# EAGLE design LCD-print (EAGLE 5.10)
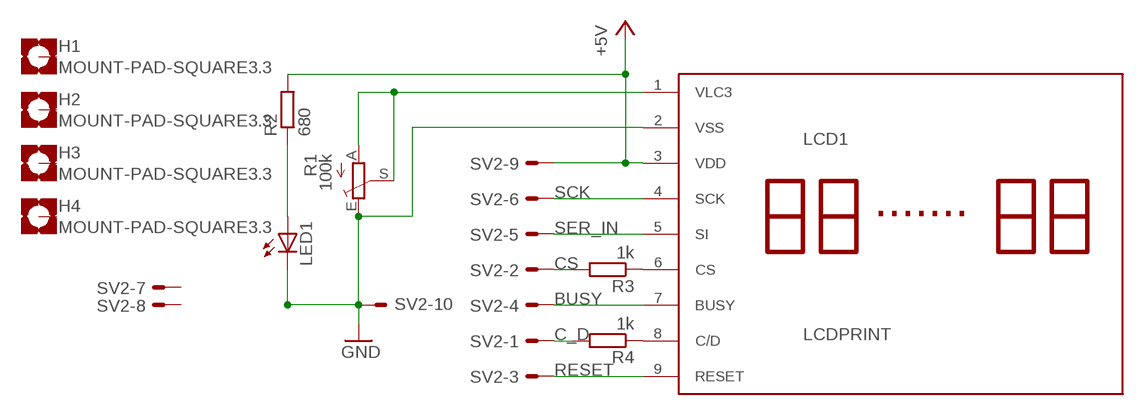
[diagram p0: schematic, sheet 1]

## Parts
H1  MOUNT-PAD-SQUARE3.3  [3,3-PAD-SQUARE]
H2  MOUNT-PAD-SQUARE3.3  [3,3-PAD-SQUARE]
H3  MOUNT-PAD-SQUARE3.3  [3,3-PAD-SQUARE]
H4  MOUNT-PAD-SQUARE3.3  [3,3-PAD-SQUARE]
LCD1  LCDPRINT  [LCD-PRINT]
LED1  LED5MM  [LED5MM]
R1  100k  TRIM_EU-CA6H  [CA6H]
R2  680  R-EU_0207/10  [0207/10]
R3  1k  R-EU_0207/10  [0207/10]
R4  1k  R-EU_0207/10  [0207/10]
SV2  ML10E  [ML10]

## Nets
+5V: LCD1.3(VDD) R2.2 SV2.9
BUSY: LCD1.7(BUSY) SV2.4
C_D: R4.2 SV2.1
CS: R3.2 SV2.2
GND: LCD1.2(VSS) LED1.K(C) R1.E SV2.10
N$1: LCD1.1(VLC3) R1.A R1.S
N$2: LED1.A R2.1
N$3: LCD1.6(CS) R3.1
N$4: LCD1.8(C/D) R4.1
RESET: LCD1.9(RESET) SV2.3
SCK: LCD1.4(SCK) SV2.6
SER_IN: LCD1.5(SI) SV2.5
Unconnected: H1.B3,3(MOUNT) H2.B3,3(MOUNT) H3.B3,3(MOUNT) H4.B3,3(MOUNT) SV2.7 SV2.8

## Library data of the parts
H1-H4 = holes:MOUNT-PAD-SQUARE: MOUNTING PAD, square
LCD1 = bar-diverse:LCD
LED1 = bar-diode-trans:LED: LED
R1 = bar-rcl:TRIM_EU-: POTENTIOMETER
R2-R4 = bar-rcl:R-EU_: RESISTOR, European symbol
SV2 = bar-con:ML10E: HARTING

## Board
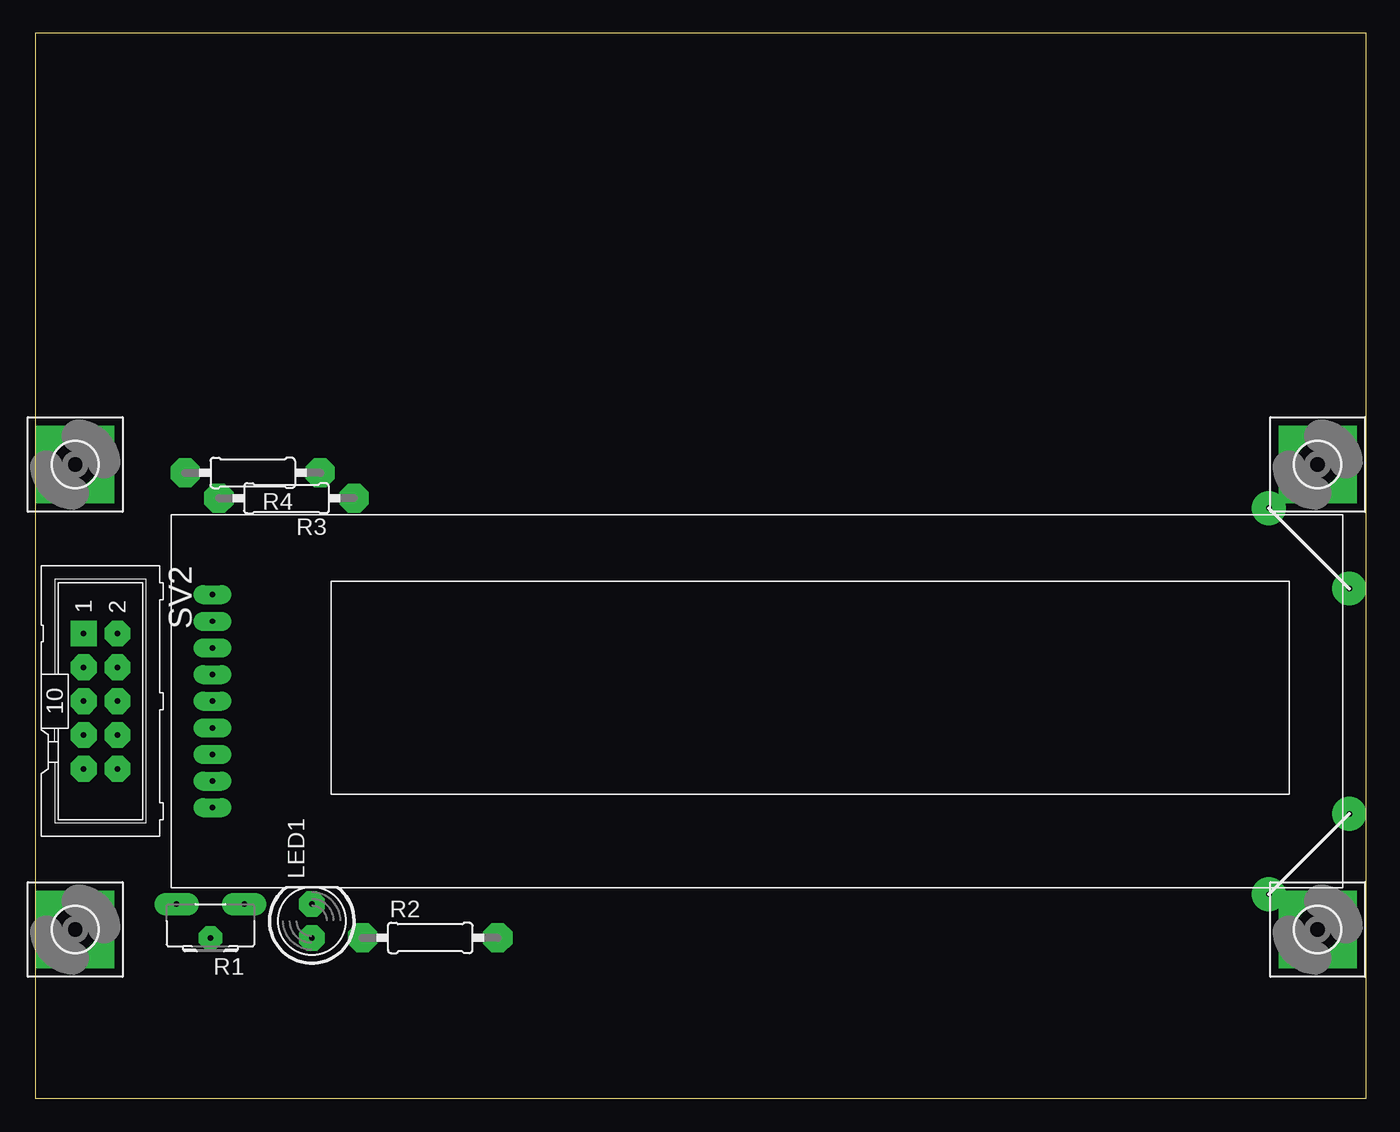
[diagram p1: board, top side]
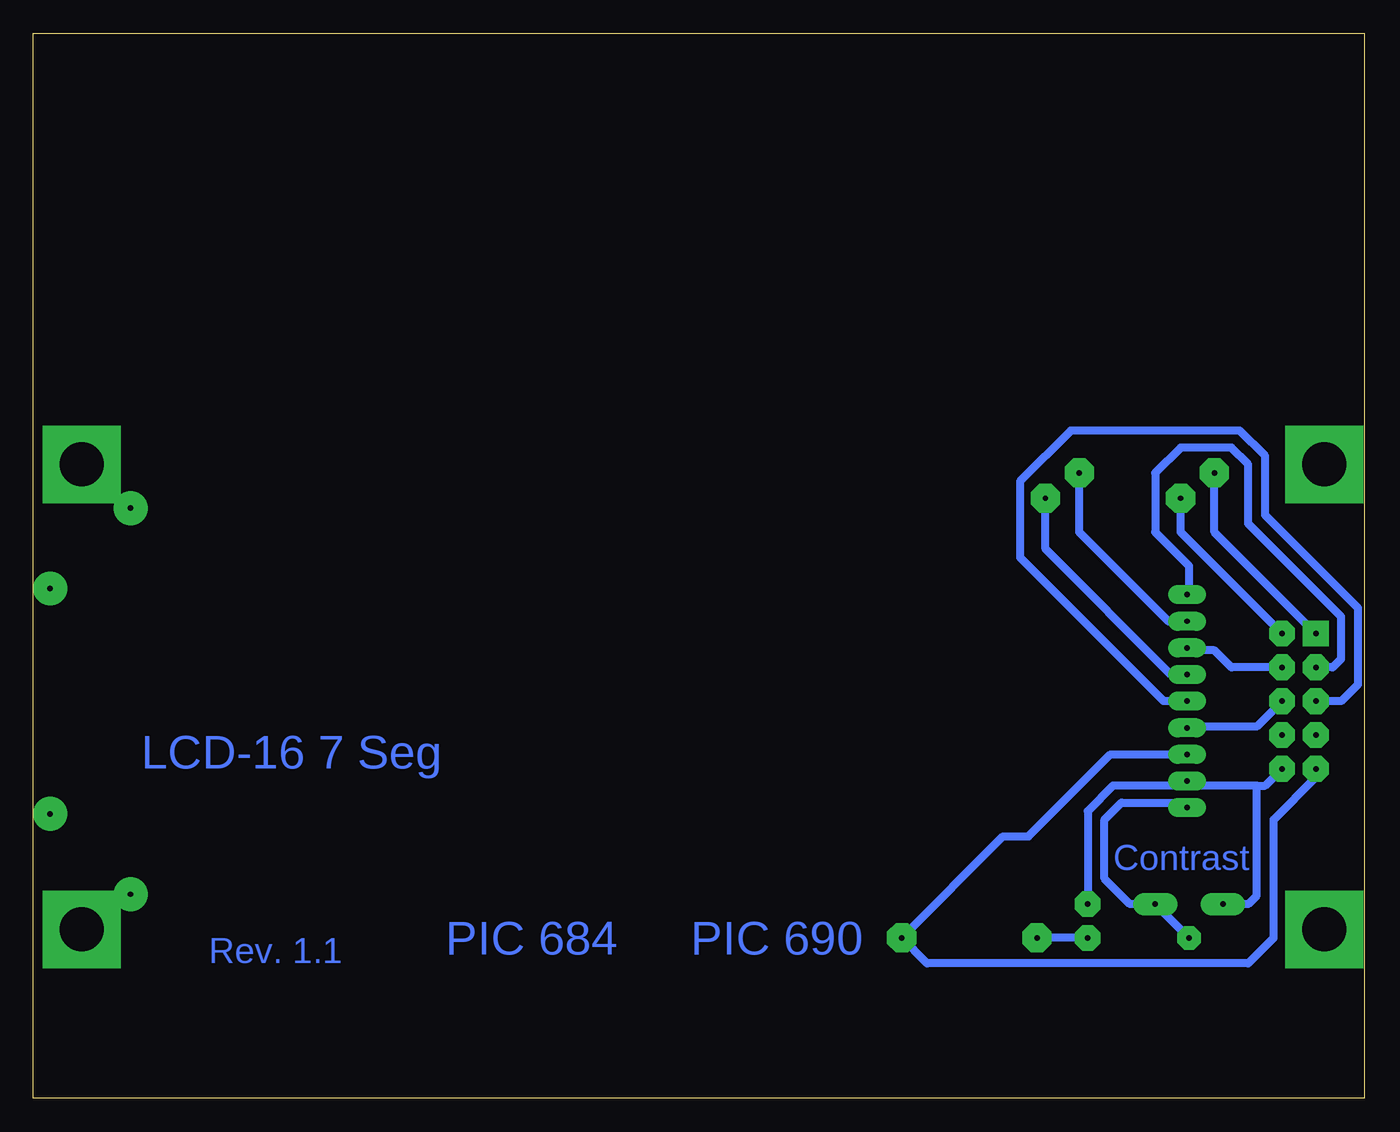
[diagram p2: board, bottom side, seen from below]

Size 100 x 80 mm. Coordinates in mm from the lower left corner, seen from the top.
Outline: 0,0 100,0 100,80 0,80 0,0
Copper layers (1*16): Top 0.035mm / dielectric 1.5mm / Bottom 0.035mm
Design rules "default": minimum track width 24mil, minimum drill 24mil, track to track 13mil, track to pad 13mil, pad to pad 13mil, via to via 13mil, smd to smd 13mil, copper to edge 40mil, drill to drill 8mil, minimum pad ring 10mil, minimum via ring 8mil, stop-mask expansion 4mil, vias tented up to drill 0mil, thermal gap 10mil

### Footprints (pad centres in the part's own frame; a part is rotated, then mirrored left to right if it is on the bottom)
3,3-PAD-SQUARE = drill 3.3 pad 5.842 square: B3,3 0,0
LCD-PRINT = drill 0.406 pad 1.422 long: 1 -11.92,-8; 2 -11.92,-6; 3 -11.92,-4; 4 -11.92,-2; 5 -11.92,0; 6 -11.92,2; 7 -11.92,4; 8 -11.92,6; 9 -11.92,8 | drill 0.406 pad 2.54 round: P$1 67.46,14.5; P$2 67.46,-14.5; P$3 73.5,-8.46; P$4 73.5,8.46
LED5MM = drill 0.406 pad 1.93 octagon: A -1.27,0; K 1.27,0
CA6H = drill 0.406 pad 1.676 long: A -2.54,0; E 2.54,0 | drill 0.406 pad 1.778 octagon: S 0,2.54
0207/10 = drill 0.406 pad 2.184 octagon: 1 -5.08,0; 2 5.08,0
ML10 = drill 0.406 pad 1.93 square: 1 -5.08,-1.27 | drill 0.406 pad 1.93 octagon: 2 -5.08,1.27; 3 -2.54,-1.27; 4 -2.54,1.27; 5 0,-1.27; 6 0,1.27; 7 2.54,-1.27; 8 2.54,1.27; 9 5.08,-1.27; 10 5.08,1.27

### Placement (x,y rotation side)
H1  96.36,12.7 0 top
H2  3.01,47.62 0 top
H3  3.01,12.7 0 top
H4  96.36,47.62 0 top
LCD1  25.23,29.84 0 top
LED1  20.79,13.33 90 top
R1  13.17,14.6 180 top
R2  29.68,12.06 0 top
R3  18.88,45.08 180 top
R4  16.34,46.98 180 top
SV2  4.92,29.84 270 top

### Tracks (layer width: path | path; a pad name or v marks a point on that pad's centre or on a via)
+5V
  Bottom 0.61: SV2.9 3.64,24.12 6.82,20.95 6.82,12.06 8.73,10.16 32.85,10.16 R2.2 27.14,19.68 25.23,19.68 19.07,25.84 LCD1.3
BUSY
  Bottom 0.61: SV2.4 10,32.38 11.27,33.65 12.54,33.65 12.68,33.8 LCD1.7
C_D
  Bottom 0.61: SV2.1 11.27,42.54 R4.2
CS
  Bottom 0.61: SV2.2 13.81,42.54 R3.2
GND
  Bottom 0.61: SV2.10 7.46,23.49 8.09,23.49 | 8.09,23.49 12.54,23.49 12.68,23.63 LCD1.2 12.68,23.98 | R1.E 8.73,14.6 8.09,15.24 8.09,23.49 | LED1.K 20.79,21.58 18.88,23.49 13.17,23.49 12.68,23.98 | 12.68,23.98 12.54,24.12
N$1
  Bottom 0.61: R1.S R1.A 17.61,14.6 19.52,16.5 19.52,20.95 18.25,22.22 12.54,22.22 12.68,22.07 LCD1.1
N$2
  Bottom 0.61: LED1.A R2.1
N$3
  Bottom 0.61: LCD1.6 14.54,31.84 23.96,41.27 R3.1
N$4
  Bottom 0.61: LCD1.8 14.73,35.84 21.42,42.54 R4.1
RESET
  Bottom 0.61: SV2.3 2.38,32.38 1.74,33.02 1.74,36.19 8.73,43.18 8.73,47.62 10,48.89 13.81,48.89 15.71,46.98 15.71,42.54 13.17,40 13.17,37.98 LCD1.9
SCK
  Bottom 0.61: SV2.6 8.09,27.93 12.54,27.93 12.63,27.84 LCD1.4
SER_IN
  Bottom 0.61: SV2.5 1.74,29.84 0.47,31.11 0.47,36.83 7.46,43.81 7.46,48.26 9.36,50.16 22.06,50.16 25.87,46.35 25.87,40.64 15.08,29.84 LCD1.5 12.54,29.84

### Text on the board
Bottom: LCD-16 7 Seg | Contrast | PIC 690 | PIC 684 | Rev. 1.1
